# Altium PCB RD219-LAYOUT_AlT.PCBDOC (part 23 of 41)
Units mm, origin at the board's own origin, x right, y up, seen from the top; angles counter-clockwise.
Board outline 209.75 x 159.97 mm, 2 copper layers (TOP, BOTTOM), stack 0 mm thick; 398 components, 199 nets, 1469 pads, 0 vias.
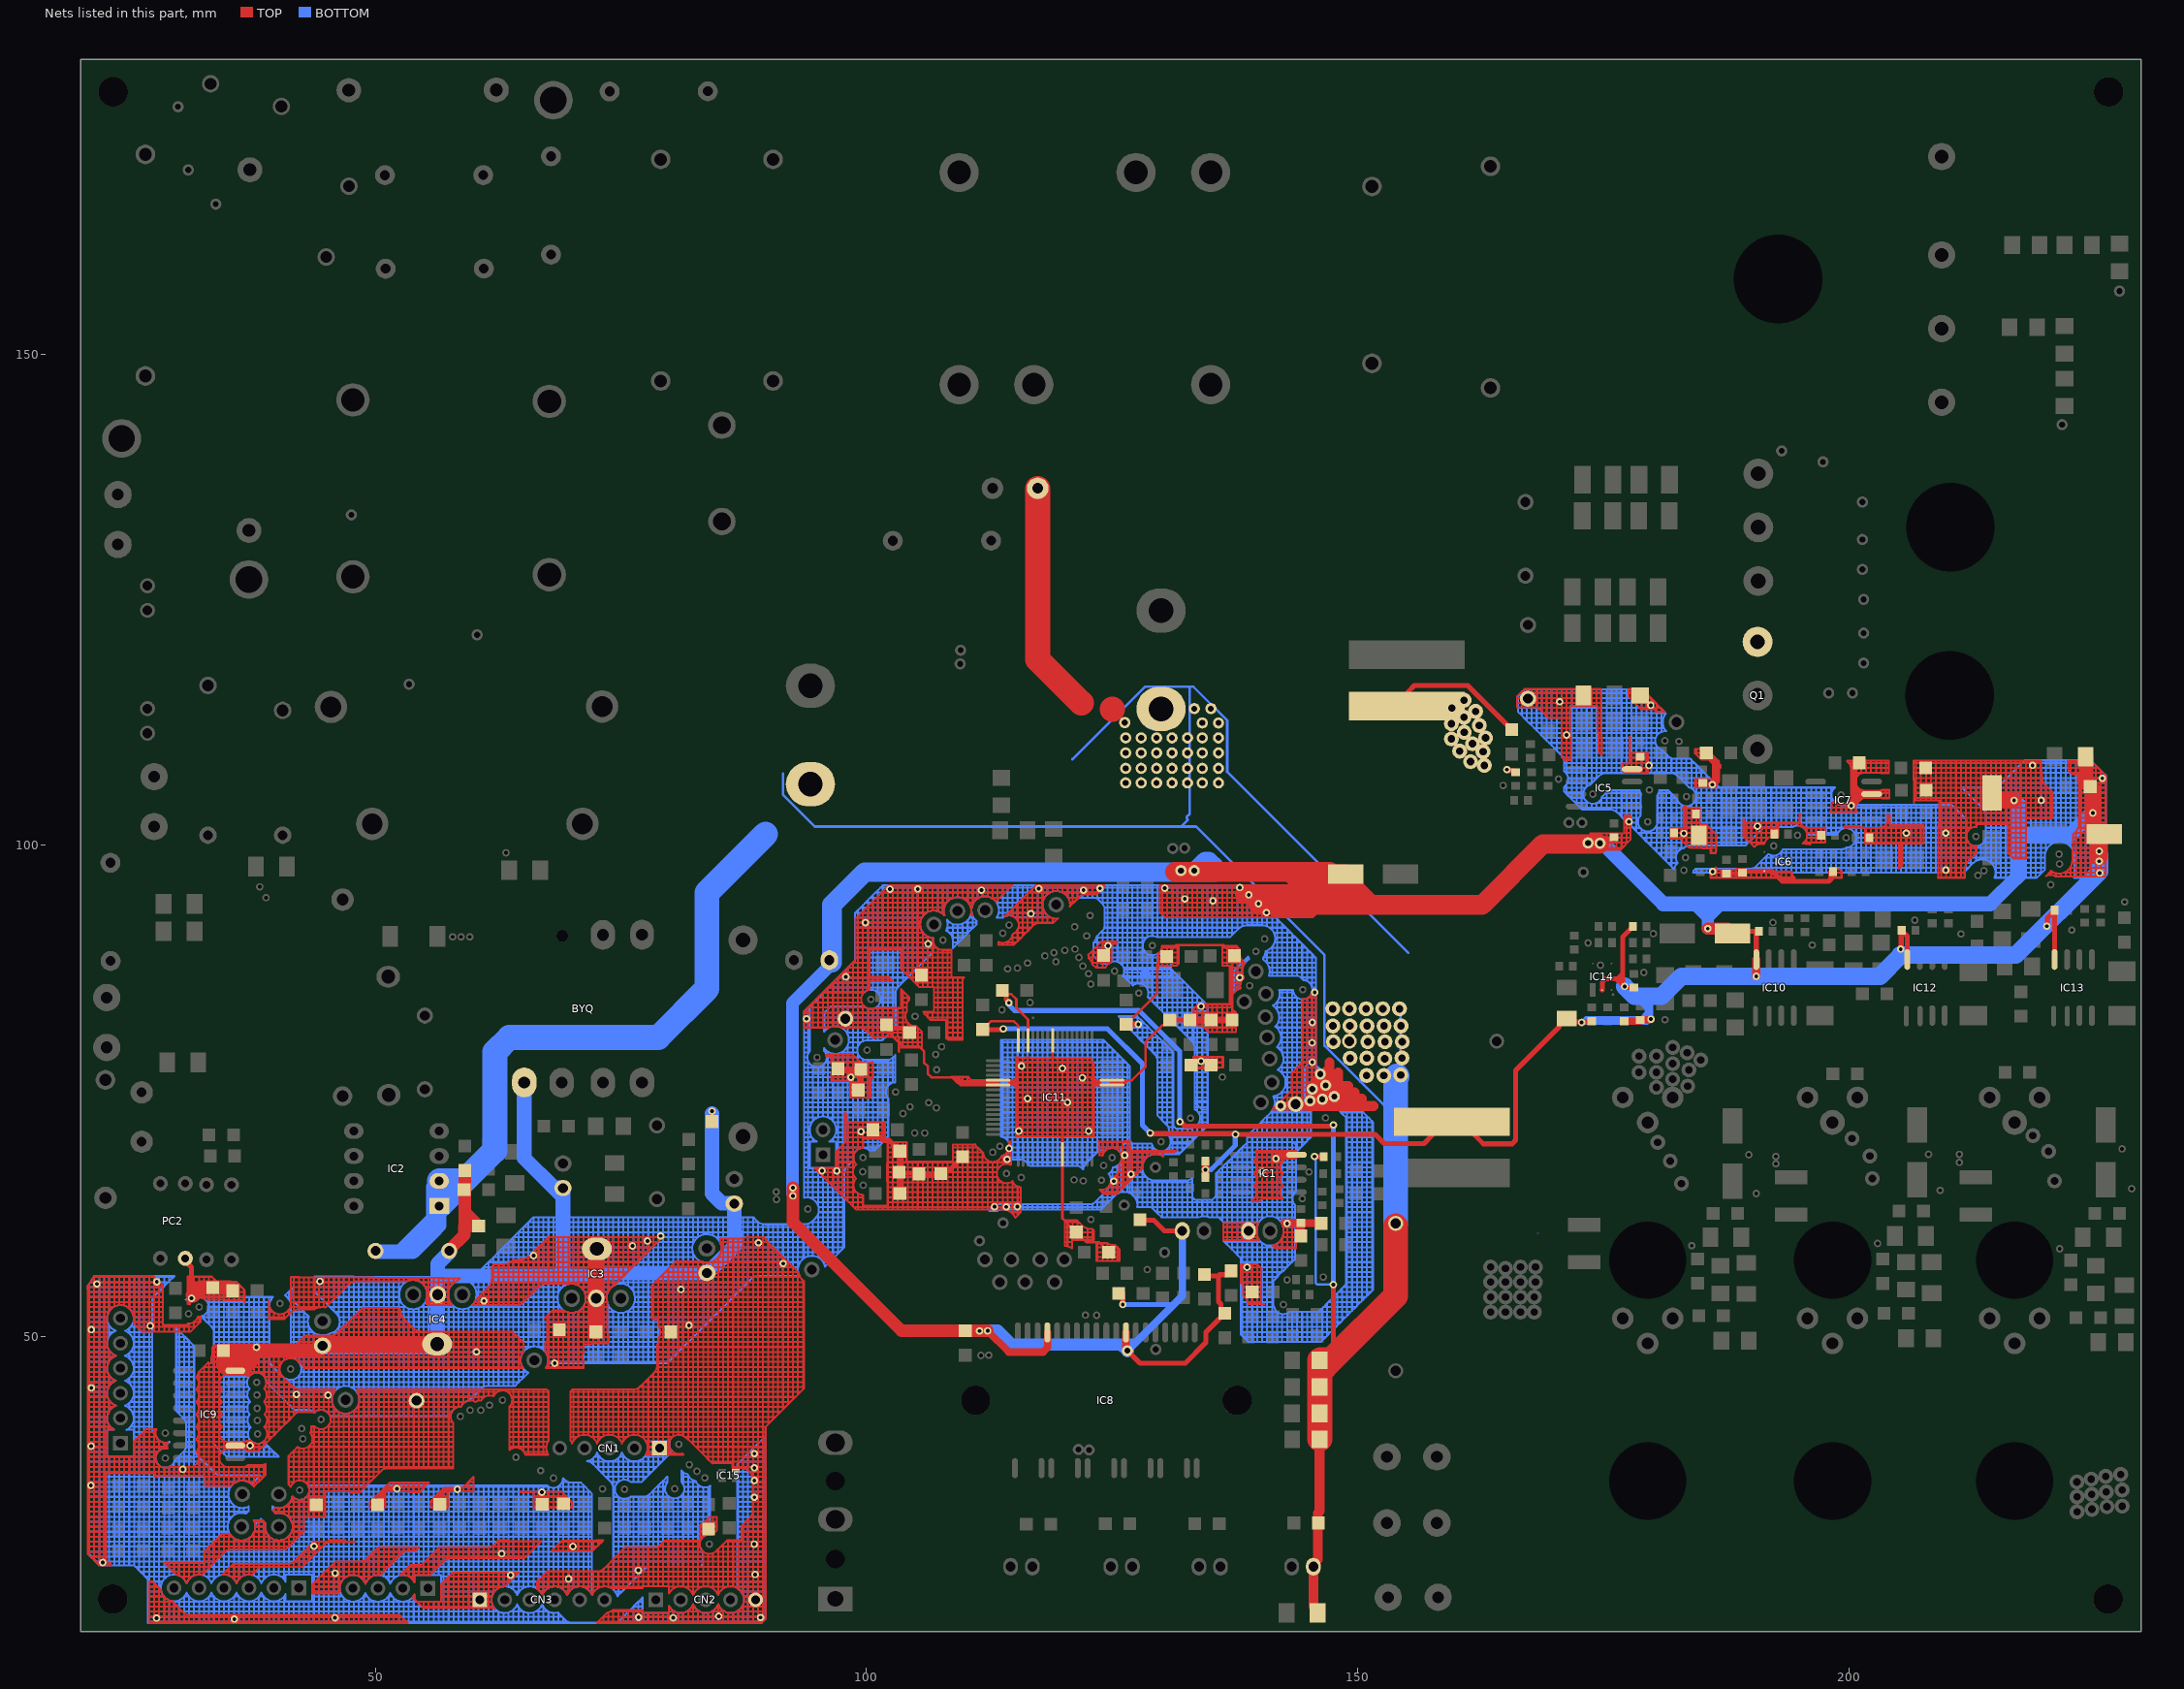
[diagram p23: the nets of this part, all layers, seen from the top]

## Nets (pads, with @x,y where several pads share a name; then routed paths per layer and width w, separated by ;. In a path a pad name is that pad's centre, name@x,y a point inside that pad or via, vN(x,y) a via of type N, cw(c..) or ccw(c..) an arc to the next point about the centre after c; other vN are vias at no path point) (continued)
GND: (continued)
  BOTTOM w0.203: 44.765,23.556 44.765,24.064 ; 44.765,23.556 45.273,23.556 ; 44.765,24.064 44.765,24.572 ; 44.765,24.064 45.273,24.064 ; 44.765,24.572 44.765,25.08 ; 44.765,24.572 45.273,24.572 ; 44.765,25.08 44.765,25.588 ; 44.765,25.08 45.273,25.08 ; 44.765,25.588 44.765,26.096 ; 44.765,25.588 45.273,25.588 ; 44.765,26.096 44.765,26.604 ; 44.765,26.096 45.273,26.096 ; 44.765,26.604 44.765,27.112 ; 44.765,26.604 45.273,26.604 ; 44.765,27.112 44.765,27.62 ; 44.765,27.112 45.273,27.112 ; 44.765,27.62 44.765,28.128 ; 44.765,27.62 45.273,27.62 ; 44.765,28.128 44.765,28.636 ; 44.765,28.128 45.273,28.128 ; 44.765,28.636 44.765,29.144 ; 44.765,28.636 45.273,28.636 ; 44.765,29.144 44.765,29.652 ; 44.765,29.144 45.273,29.144 ; 44.765,29.652 44.765,30.16 ; 44.765,29.652 45.273,29.652 ; 44.765,30.16 44.765,30.668 ; 44.765,30.16 45.273,30.16 ; 44.765,30.668 44.765,31.176 ; 44.765,30.668 45.273,30.668 ; 44.765,31.176 44.765,31.684 ; 44.765,31.176 45.273,31.176 ; 44.765,31.684 44.765,32.192 ; 44.765,31.684 45.273,31.684 ; 44.765,32.192 44.765,32.7 ; 44.765,32.192 45.273,32.192 ; 44.765,32.7 44.765,33.208 ; 44.765,32.7 45.273,32.7 ; 44.765,33.208 44.765,33.716 ; 44.765,33.208 45.273,33.208 ; 44.765,33.716 44.765,34.224 ; 44.765,33.716 45.273,33.716 ; 44.765,34.224 44.765,34.732 ; 44.765,34.224 45.273,34.224 ; 44.765,34.732 44.765,34.866 ; 44.765,34.732 45.273,34.732 ; 44.765,34.866 45.273,34.866 ; 44.765,42.531 cw(c44.482,41.59) 45.101,42.354 cw(c44.482,41.59) 45.103,42.352 ; 44.765,42.531 44.765,42.86 ; 44.765,42.86 44.765,43.368 ; 44.765,42.86 45.273,42.86 ; 44.765,43.368 44.765,43.876 ; 44.765,43.368 45.273,43.368 ; 44.765,43.876 pad.@45.273,43.876 ; 44.765,43.876 44.765,44.384 ; 44.765,44.384 44.765,44.892 ; 44.765,44.384 pad.@45.273,44.384 ; 44.765,44.892 44.765,45.4 ; 44.765,44.892 45.273,44.892 ; 44.765,45.4 45.273,45.4 ; 44.765,45.4 44.765,45.908 ; 44.765,45.908 44.765,46.416 ; 44.765,45.908 45.273,45.908 ; 44.765,46.416 44.765,46.924 ; 44.765,46.416 45.273,46.416 ; 44.765,46.924 44.765,47.432 ; 44.765,46.924 45.273,46.924 ; 44.765,47.432 44.765,47.94 ; 44.765,47.432 45.273,47.432 ; 44.765,47.94 EC6.2@44.765,48.448 ; 44.765,47.94 45.273,47.94 ; EC6.2@44.765,48.448 EC6.2@44.765,48.956 ; EC6.2@44.765,48.448 45.273,48.448 ; EC6.2@44.765,48.956 44.765,49.06 EC6.2@44.765,49.464 ; EC6.2@44.765,48.956 44.869,48.956 EC6.2@45.273,48.956 ; EC6.2@44.765,49.464 44.765,49.972 ; EC6.2@44.765,49.464 EC6.2@45.273,49.464 ; 44.765,49.972 45.273,49.972 ; 44.765,49.972 44.765,50.157 ; 44.765,50.157 ccw(c44.702,51.583) 45.273,50.275 ; 44.765,54.036 44.765,54.544 ; 44.765,54.036 45.273,54.036 ; 44.765,54.544 44.765,55.052 ; 44.765,54.544 45.273,54.544 ; 44.765,55.052 44.765,55.56 ; 44.765,55.052 45.273,55.052 ; 44.765,55.56 45.273,55.56 ; 44.765,55.56 44.765,56.068 ; 44.765,56.068 44.765,56.118 ; 44.765,56.068 45.273,56.068 ; 44.765,56.118 45.273,56.116 ; 44.872,53.528 45.273,53.127 ; 44.872,53.528 45.273,53.528 ; 45.103,42.352 cw(c44.482,41.59) 45.273,42.173 ; 45.103,42.352 45.273,42.352 ; 45.273,20.889 45.273,21.016 ; 45.273,20.889 45.781,20.889 ; 45.273,21.016 45.273,21.524 ; 45.273,21.016 45.781,21.016 ; 45.273,21.524 45.273,22.032 ; 45.273,21.524 pad.@45.781,21.524 ; 45.273,22.032 45.273,22.54 ; 45.273,22.032 45.781,22.032 ; 45.273,22.54 45.273,23.048 ; 45.273,22.54 45.781,22.54 ; 45.273,23.048 45.273,23.556 ; 45.273,23.048 45.781,23.048 ; 45.273,23.556 45.273,24.064 ; 45.273,23.556 45.781,23.556 ; 45.273,24.064 45.273,24.572 ; 45.273,24.064 45.781,24.064 ; 45.273,24.572 45.273,25.08 ; 45.273,24.572 45.781,24.572 ; 45.273,25.08 45.273,25.588 ; 45.273,25.08 45.781,25.08 ; 45.273,25.588 45.273,26.096 ; 45.273,25.588 pad.@45.781,25.588 ; 45.273,26.096 45.273,26.604 ; 45.273,26.096 pad.@45.781,26.096 ; 45.273,26.604 45.273,27.112 ; 45.273,26.604 45.781,26.604 ; 45.273,27.112 45.273,27.62 ; 45.273,27.112 45.781,27.112 ; 45.273,27.62 45.273,28.128 ; 45.273,27.62 45.781,27.62 ; 45.273,28.128 45.273,28.636 ; 45.273,28.128 45.781,28.128 ; 45.273,28.636 45.273,29.144 ; 45.273,28.636 45.781,28.636 ; 45.273,29.144 45.273,29.652 ; 45.273,29.144 45.781,29.144 ; 45.273,29.652 45.273,30.16 ; 45.273,29.652 45.781,29.652 ; 45.273,30.16 45.273,30.668 ; 45.273,30.16 45.781,30.16 ; 45.273,30.668 45.273,31.176 ; 45.273,30.668 45.781,30.668 ; 45.273,31.176 45.273,31.684 ; 45.273,31.176 45.781,31.176 ; 45.273,31.684 45.273,32.192 ; 45.273,31.684 45.781,31.684 ; 45.273,32.192 45.273,32.7 ; 45.273,32.192 45.781,32.192 ; 45.273,32.7 45.273,33.208 ; 45.273,32.7 45.781,32.7 ; 45.273,33.208 45.273,33.716 ; 45.273,33.208 45.781,33.208 ; 45.273,33.716 45.273,34.224 ; 45.273,33.716 45.781,33.716 ; 45.273,34.224 45.273,34.732 ; 45.273,34.224 45.781,34.224 ; 45.273,34.732 45.273,34.866 ; 45.273,34.732 45.781,34.732 ; 45.273,34.866 45.781,34.866 ; 45.273,42.173 45.273,42.352 ; 45.273,42.352 45.273,42.86 ; 45.273,42.352 45.781,42.352 ; 45.273,42.86 45.273,43.368 ; 45.273,42.86 45.774,42.86 ; 45.273,43.368 pad.@45.273,43.876 ; 45.273,43.368 45.593,43.368 ; pad.@45.273,43.876 pad.@45.273,44.384 ; pad.@45.273,43.876 45.61,43.876 ; pad.@45.273,44.384 45.781,44.384 ; pad.@45.273,44.384 45.273,44.892 ; 45.273,44.892 45.273,45.4 ; 45.273,44.892 45.781,44.892 ; 45.273,45.4 45.781,45.4 ; 45.273,45.4 45.273,45.908 ; 45.273,45.908 45.273,46.416 ; 45.273,45.908 45.781,45.908 ; 45.273,46.416 45.273,46.924 ; 45.273,46.416 45.781,46.416 ; 45.273,46.924 45.273,47.432 ; 45.273,46.924 45.781,46.924 ; 45.273,47.432 45.273,47.94 ; 45.273,47.432 45.781,47.432 ; 45.273,47.94 45.273,48.448 ; 45.273,47.94 45.781,47.94 ; 45.273,48.448 EC6.2@45.273,48.956 ; 45.273,48.448 45.781,48.448 ; EC6.2@45.273,48.956 45.781,48.956 ; EC6.2@45.273,48.956 EC6.2@45.273,49.464 ; EC6.2@45.273,49.464 45.273,49.972 ; EC6.2@45.273,49.464 45.781,49.464 ; 45.273,49.972 45.781,49.972 ; 45.273,49.972 45.273,50.275 ; 45.273,50.275 ccw(c44.702,51.583) 45.452,50.369 ; 45.273,53.127 45.273,53.528 ; 45.273,53.127 45.38,53.02 ; 45.273,53.528 45.273,54.036 ; 45.273,53.528 45.781,53.528 ; 45.273,54.036 45.273,54.544 ; 45.273,54.036 45.781,54.036 ; 45.273,54.544 45.273,55.052 ; 45.273,54.544 45.781,54.544 ; 45.273,55.052 45.273,55.56 ; 45.273,55.052 45.781,55.052 ; 45.273,55.56 45.273,56.068 ; 45.273,55.56 45.781,55.56 ; 45.273,56.068 45.273,56.116 ; 45.273,56.068 45.781,56.068 ; 45.273,56.116 45.781,56.115 ; 45.38,53.02 45.781,53.02 ; 45.38,53.02 45.781,52.619 ; 45.593,43.368 cw(c46.979,43.576) 45.608,43.868 cw(c46.979,43.576) 45.61,43.876 ; 45.593,43.368 ccw(c46.979,43.576) 45.595,43.357 ccw(c46.979,43.576) 45.774,42.86 ; 45.774,42.86 ccw(c46.979,43.576) 45.781,42.849 ; 45.781,20.889 45.781,21.016 ; 45.781,20.889 46.289,20.889 ; 45.781,21.016 46.289,21.016 ; 45.781,21.016 pad.@45.781,21.524 ; pad.@45.781,21.524 45.781,22.032 ; pad.@45.781,21.524 46.289,21.524 ; 45.781,22.032 45.781,22.54 ; 45.781,22.032 46.289,22.032 ; 45.781,22.54 45.781,23.048 ; 45.781,22.54 46.289,22.54 ; 45.781,23.048 45.781,23.556 ; 45.781,23.048 46.289,23.048 ; 45.781,23.556 45.781,24.064 ; 45.781,23.556 46.289,23.556 ; 45.781,24.064 45.781,24.572 ; 45.781,24.064 46.289,24.064 ; 45.781,24.572 45.781,25.08 ; 45.781,24.572 46.289,24.572 ; 45.781,25.08 pad.@45.781,25.588 ; 45.781,25.08 46.289,25.08 ; pad.@45.781,25.588 46.289,25.588 ; pad.@45.781,25.588 pad.@45.781,26.096 ; pad.@45.781,26.096 45.781,26.604 ; pad.@45.781,26.096 46.289,26.096 ; 45.781,26.604 45.781,27.112 ; 45.781,26.604 46.289,26.604 ; 45.781,27.112 45.781,27.62 ; 45.781,27.112 46.289,27.112 ; 45.781,27.62 45.781,28.128 ; 45.781,27.62 46.289,27.62 ; 45.781,28.128 45.781,28.636 ; 45.781,28.128 46.289,28.128 ; 45.781,28.636 45.781,29.144 ; 45.781,28.636 46.289,28.636 ; 45.781,29.144 45.781,29.652 ; 45.781,29.144 46.289,29.144 ; 45.781,29.652 45.781,30.16 ; 45.781,29.652 46.289,29.652 ; 45.781,30.16 45.781,30.668 ; 45.781,30.16 46.289,30.16 ; 45.781,30.668 45.781,31.176 ; 45.781,30.668 46.289,30.668 ; 45.781,31.176 45.781,31.684 ; 45.781,31.176 46.289,31.176 ; 45.781,31.684 45.781,32.192 ; 45.781,31.684 46.289,31.684 ; 45.781,32.192 45.781,32.7 ; 45.781,32.192 46.289,32.192 ; 45.781,32.7 45.781,33.208 ; 45.781,32.7 46.289,32.7 ; 45.781,33.208 45.781,33.716 ; 45.781,33.208 46.289,33.208 ; 45.781,33.716 45.781,34.224 ; 45.781,33.716 46.289,33.716 ; 45.781,34.224 45.781,34.732 ; 45.781,34.224 46.289,34.224 ; 45.781,34.732 45.781,34.866 ; 45.781,34.732 46.289,34.732 ; 45.781,34.866 46.289,34.866 ; 45.781,41.938 45.781,42.352 ; 45.781,41.938 46.289,41.938 ; 45.781,42.352 46.289,42.352 ; 45.781,42.352 45.781,42.849 ; 45.781,44.384 45.781,44.892 ; 45.781,44.384 45.833,44.384 ; 45.781,44.892 45.781,45.4 ; 45.781,44.892 46.289,44.892 ; 45.781,45.4 46.289,45.4 ; 45.781,45.4 45.781,45.908 ; 45.781,45.908 45.781,46.416 ; 45.781,45.908 46.289,45.908 ; 45.781,46.416 46.289,46.416 ; 45.781,46.416 45.781,46.924 ; 45.781,46.924 45.781,47.432 ; 45.781,46.924 46.289,46.924 ; 45.781,47.432 46.289,47.432 ; 45.781,47.432 45.781,47.94 ; 45.781,47.94 45.781,48.448 ; 45.781,47.94 46.289,47.94 ; 45.781,48.448 45.781,48.956 ; 45.781,48.448 46.289,48.448 ; 45.781,48.956 45.781,49.464 ; 45.781,48.956 46.289,48.956 ; 45.781,49.464 45.781,49.972 ; 45.781,49.464 46.289,49.464 ; 45.781,49.972 46.289,49.972 ; 45.781,52.619 45.888,52.512 ; 45.781,52.619 45.781,53.02 ; 45.781,53.02 45.781,53.528 ; 45.781,53.02 46.289,53.02 ; 45.781,53.528 45.781,54.036 ; 45.781,53.528 46.289,53.528 ; 45.781,54.036 45.781,54.544 ; 45.781,54.036 46.289,54.036 ; 45.781,54.544 45.781,55.052 ; 45.781,54.544 46.289,54.544 ; 45.781,55.052 45.781,55.56 ; 45.781,55.052 46.289,55.052 ; 45.781,55.56 45.781,56.068 ; 45.781,55.56 46.289,55.56 ; 45.781,56.068 45.781,56.115 ; 45.781,56.068 46.289,56.068 ; 45.781,56.115 46.289,56.113 ; 45.833,44.384 cw(c46.979,43.576) 46.289,44.796 ; 45.888,52.512 46.051,52.349 ; 45.888,52.512 46.289,52.512 ; 46.052,52.348 cw(c45.273,51.569) 46.285,52.004 ; 46.052,52.348 cw(c45.273,51.569) 46.285,52.004 ; 46.27,50.988 ccw(c45.273,51.456) 46.289,51.03 ; 46.27,50.988 46.289,50.988 ; 46.285,52.004 cw(c45.273,51.569) 46.287,51.999 ; 46.285,52.004 cw(c45.273,51.569) 46.287,51.999 ; 46.285,52.004 46.289,52.004 ; 46.287,51.999 cw(c45.273,51.569) 46.289,51.994 ; 46.287,51.999 cw(c45.273,51.569) 46.289,51.994 ; 46.289,20.889 46.289,21.016 ; 46.289,20.889 46.797,20.889 ; 46.289,21.016 46.797,21.016 ; 46.289,21.016 46.289,21.524 ; 46.289,21.524 46.289,22.032 ; 46.289,21.524 46.797,21.524 ; 46.289,22.032 46.289,22.54 ; 46.289,22.032 46.797,22.032 ; 46.289,22.54 46.289,23.048 ; 46.289,22.54 46.797,22.54 ; 46.289,23.048 46.289,23.556 ; 46.289,23.048 46.797,23.048 ; 46.289,23.556 46.289,24.064 ; 46.289,23.556 46.671,23.556 ; 46.289,24.064 46.289,24.572 ; 46.289,24.064 46.419,24.064 ; 46.289,24.572 46.289,25.08 ; 46.289,25.08 46.289,25.588 ; 46.289,25.08 46.562,25.08 ; 46.289,25.588 46.797,25.588 ; 46.289,25.588 46.289,26.096 ; 46.289,26.096 46.289,26.604 ; 46.289,26.096 46.797,26.096 ; 46.289,26.604 46.289,27.112 ; 46.289,26.604 46.797,26.604 ; 46.289,27.112 46.289,27.62 ; 46.289,27.112 46.797,27.112 ; 46.289,27.62 46.289,28.128 ; 46.289,27.62 46.797,27.62 ; 46.289,28.128 46.289,28.636 ; 46.289,28.128 46.797,28.128 ; 46.289,28.636 46.289,29.144 ; 46.289,28.636 46.797,28.636 ; 46.289,29.144 46.289,29.652 ; 46.289,29.144 46.797,29.144 ; 46.289,29.652 46.289,30.16 ; 46.289,29.652 46.797,29.652 ; 46.289,30.16 46.289,30.668 ; 46.289,30.16 46.797,30.16 ; 46.289,30.668 46.289,31.176 ; 46.289,30.668 46.797,30.668 ; 46.289,31.176 46.289,31.684 ; 46.289,31.176 46.797,31.176 ; 46.289,31.684 46.289,32.192 ; 46.289,31.684 46.797,31.684 ; 46.289,32.192 46.289,32.7 ; 46.289,32.192 46.797,32.192 ; 46.289,32.7 46.289,33.208 ; 46.289,32.7 46.797,32.7 ; 46.289,33.208 46.289,33.716 ; 46.289,33.208 46.797,33.208 ; 46.289,33.716 46.289,34.224 ; 46.289,33.716 46.797,33.716 ; 46.289,34.224 46.289,34.732 ; 46.289,34.224 46.797,34.224 ; 46.289,34.732 46.289,34.866 ; 46.289,34.732 46.797,34.732 ; 46.289,34.866 46.797,34.866 ; 46.289,41.938 46.289,42.352 ; 46.289,41.938 46.797,41.938 ; 46.289,44.796 cw(c46.979,43.576) 46.3,44.802 cw(c46.979,43.576) 46.495,44.892 ; 46.289,44.796 46.289,44.892 ; 46.289,44.892 46.289,45.4 ; 46.289,44.892 46.495,44.892 ; 46.289,45.4 46.797,45.4 ; 46.289,45.4 46.289,45.908 ; 46.289,45.908 46.289,46.416 ; 46.289,45.908 46.797,45.908 ; 46.289,46.416 46.289,46.924 ; 46.289,46.416 46.797,46.416 ; 46.289,46.924 46.289,47.432 ; 46.289,46.924 46.797,46.924 ; 46.289,47.432 46.797,47.432 ; 46.289,47.432 46.289,47.94 ; 46.289,47.94 46.289,48.448 ; 46.289,47.94 46.797,47.94 ; 46.289,48.448 46.289,48.956 ; 46.289,48.448 46.797,48.448 ; 46.289,48.956 46.289,49.464 ; 46.289,48.956 46.797,48.956 ; 46.289,49.464 46.289,49.972 ; 46.289,49.464 46.797,49.464 ; 46.289,49.972 46.289,50.48 ; 46.289,49.972 46.797,49.972 ; 46.289,50.48 46.289,50.988 ; 46.289,50.48 46.797,50.48 ; 46.289,50.988 46.797,50.988 ; 46.289,50.988 46.289,51.03 ; 46.289,51.03 ccw(c45.273,51.456) 46.375,51.456 46.375,51.496 ; 46.289,51.994 cw(c45.273,51.569) 46.375,51.569 ; 46.289,51.994 cw(c45.273,51.569) 46.375,51.569 ; 46.289,51.994 46.289,52.004 ; 46.289,52.004 46.797,52.004 ; 46.289,52.004 46.289,52.512 ; 46.289,52.512 46.289,53.02 ; 46.289,52.512 46.797,52.512 ; 46.289,53.02 46.289,53.528 ; 46.289,53.02 46.797,53.02 ; 46.289,53.528 46.289,54.036 ; 46.289,53.528 46.797,53.528 ; 46.289,54.036 46.289,54.544 ; 46.289,54.036 46.797,54.036 ; 46.289,54.544 46.289,55.052 ; 46.289,54.544 46.797,54.544 ; 46.289,55.052 46.289,55.56 ; 46.289,55.052 46.797,55.052 ; 46.289,55.56 46.289,56.068 ; 46.289,55.56 46.797,55.56 ; 46.289,56.068 46.289,56.113 ; 46.289,56.068 46.797,56.068 ; 46.289,56.113 46.797,56.111 ; 46.375,51.496 46.375,51.569 ; 46.375,51.496 46.797,51.496 ; 46.419,24.064 ccw(c47.729,24.397) 46.671,23.556 ; 46.495,44.892 cw(c46.979,43.576) 46.5,44.894 cw(c46.979,43.576) 46.797,44.966 ; 46.671,23.556 ccw(c47.729,24.397) 46.79,23.425 ccw(c47.729,24.397) 46.797,23.418 ; 46.797,20.889 46.797,21.016 ; 46.797,20.889 47.305,20.889 ; 46.797,21.016 46.797,21.524 ; 46.797,21.016 47.305,21.016 ; 46.797,21.524 46.797,22.032 ; 46.797,21.524 47.305,21.524 ; 46.797,22.032 46.797,22.54 ; 46.797,22.032 47.305,22.032 ; 46.797,22.54 46.797,23.048 ; 46.797,22.54 47.305,22.54 ; 46.797,23.048 47.305,23.048 ; 46.797,23.048 46.797,23.418 ; 46.797,25.588 46.797,26.096 ; 46.797,25.588 47.09,25.588 ; 46.797,26.096 46.797,26.604 ; 46.797,26.096 47.305,26.096 ; 46.797,26.604 46.797,27.112 ; 46.797,26.604 47.305,26.604 ; 46.797,27.112 46.797,27.62 ; 46.797,27.112 47.305,27.112 ; 46.797,27.62 46.797,28.128 ; 46.797,27.62 47.305,27.62 ; 46.797,28.128 46.797,28.636 ; 46.797,28.128 47.305,28.128 ; 46.797,28.636 46.797,29.144 ; 46.797,28.636 47.305,28.636 ; 46.797,29.144 46.797,29.652 ; 46.797,29.144 47.305,29.144 ; 46.797,29.652 46.797,30.16 ; 46.797,29.652 47.305,29.652 ; 46.797,30.16 46.797,30.668 ; 46.797,30.16 47.305,30.16 ; 46.797,30.668 46.797,31.176 ; 46.797,30.668 47.305,30.668 ; 46.797,31.176 46.797,31.684 ; 46.797,31.176 47.305,31.176 ; 46.797,31.684 46.797,32.192 ; 46.797,31.684 47.305,31.684 ; 46.797,32.192 46.797,32.7 ; 46.797,32.192 47.305,32.192 ; 46.797,32.7 46.797,33.208 ; 46.797,32.7 47.305,32.7 ; 46.797,33.208 46.797,33.716 ; 46.797,33.208 47.305,33.208 ; 46.797,33.716 46.797,34.224 ; 46.797,33.716 47.305,33.716 ; 46.797,34.224 46.797,34.732 ; 46.797,34.224 47.305,34.224 ; 46.797,34.732 46.797,34.866 ; 46.797,34.732 47.305,34.732 ; 46.797,34.866 47.305,34.866 ; 46.797,41.938 47.305,41.938 ; 46.797,41.938 46.797,42.187 ; 46.797,42.187 ccw(c46.979,43.576) 46.808,42.185 ccw(c46.979,43.576) 47.305,42.213 ; 46.797,44.966 cw(c46.979,43.576) 47.305,44.94 ; 46.797,44.966 46.797,45.4 ; 46.797,45.4 47.305,45.4 ; 46.797,45.4 46.797,45.908 ; 46.797,45.908 46.797,46.416 ; 46.797,45.908 47.305,45.908 ; 46.797,46.416 47.305,46.416 ; 46.797,46.416 46.797,46.924 ; 46.797,46.924 46.797,47.432 ; 46.797,46.924 47.305,46.924 ; 46.797,47.432 47.305,47.432 ; 46.797,47.432 46.797,47.94 ; 46.797,47.94 46.797,48.448 ; 46.797,47.94 47.305,47.94 ; 46.797,48.448 46.797,48.956 ; 46.797,48.448 47.305,48.448 ; 46.797,48.956 46.797,49.464 ; 46.797,48.956 47.305,48.956 ; 46.797,49.464 46.797,49.972 ; 46.797,49.464 47.305,49.464 ; 46.797,49.972 46.797,50.48 ; 46.797,49.972 47.305,49.972 ; 46.797,50.48 46.797,50.988 ; 46.797,50.48 47.305,50.48 ; 46.797,50.988 47.305,50.988 ; 46.797,50.988 46.797,51.496 ; 46.797,51.496 47.305,51.496 ; 46.797,51.496 46.797,52.004 ; 46.797,52.004 46.797,52.512 ; 46.797,52.004 47.305,52.004 ; 46.797,52.512 46.797,53.02 ; 46.797,52.512 47.305,52.512 ; 46.797,53.02 46.797,53.528 ; 46.797,53.02 47.305,53.02 ; 46.797,53.528 46.797,54.036 ; 46.797,53.528 47.305,53.528 ; 46.797,54.036 47.305,54.036 ; 46.797,54.036 46.797,54.544 ; 46.797,54.544 47.305,54.544 ; 46.797,54.544 46.797,55.052 ; 46.797,55.052 46.797,55.56 ; 46.797,55.052 47.305,55.052 ; 46.797,55.56 46.797,56.068 ; 46.797,55.56 47.305,55.56 ; 46.797,56.068 47.305,56.068 ; 46.797,56.068 46.797,56.111 ; 46.797,56.111 47.305,56.11 ; 47.09,25.588 cw(c47.729,24.397) 47.094,25.59 cw(c47.729,24.397) 47.305,25.68 ; 47.305,20.889 47.305,21.016 ; 47.305,20.889 47.813,20.889 ; 47.305,21.016 47.305,21.524 ; 47.305,21.016 47.813,21.016 ; 47.305,21.524 47.305,22.032 ; 47.305,21.524 47.813,21.524 ; 47.305,22.032 47.305,22.54 ; 47.305,22.032 47.813,22.032 ; 47.305,22.54 47.305,23.048 ; 47.305,22.54 47.813,22.54 ; 47.305,23.048 47.645,23.048 ; 47.305,25.68 cw(c47.729,24.397) 47.311,25.682 cw(c47.729,24.397) 47.813,25.746 ; 47.305,25.68 47.305,26.096 ; 47.305,26.096 47.305,26.604 ; 47.305,26.096 47.813,26.096 ; 47.305,26.604 47.305,27.112 ; 47.305,26.604 47.813,26.604 ; 47.305,27.112 47.305,27.62 ; 47.305,27.112 47.813,27.112 ; 47.305,27.62 47.305,28.128 ; 47.305,27.62 47.813,27.62 ; 47.305,28.128 47.305,28.636 ; 47.305,28.128 47.813,28.128 ; 47.305,28.636 47.305,29.144 ; 47.305,28.636 47.813,28.636 ; 47.305,29.144 47.305,29.652 ; 47.305,29.144 47.813,29.144 ; 47.305,29.652 47.305,30.16 ; 47.305,29.652 47.813,29.652 ; 47.305,30.16 47.305,30.668 ; 47.305,30.16 47.813,30.16 ; 47.305,30.668 47.305,31.176 ; 47.305,30.668 47.813,30.668 ; 47.305,31.176 47.305,31.684 ; 47.305,31.176 47.813,31.176 ; 47.305,31.684 47.305,32.192 ; 47.305,31.684 47.813,31.684 ; 47.305,32.192 47.305,32.7 ; 47.305,32.192 47.813,32.192 ; 47.305,32.7 47.305,33.208 ; 47.305,32.7 47.813,32.7 ; 47.305,33.208 47.305,33.716 ; 47.305,33.208 47.813,33.208 ; 47.305,33.716 47.305,34.224 ; 47.305,33.716 47.813,33.716 ; 47.305,34.224 47.305,34.732 ; 47.305,34.224 47.813,34.224 ; 47.305,34.732 47.305,34.866 ; 47.305,34.732 47.813,34.732 ; 47.305,34.866 47.813,34.866 ; 47.305,41.938 47.813,41.938 ; 47.305,41.938 47.305,42.213 ; 47.305,42.213 ccw(c46.979,43.576) 47.661,42.352 ; 47.305,44.94 47.305,45.4 ; 47.305,45.4 47.305,45.908 ; 47.305,45.4 47.813,45.4 ; 47.305,45.908 47.305,46.416 ; 47.305,45.908 47.813,45.908 ; 47.305,46.416 47.305,46.924 ; 47.305,46.416 47.813,46.416 ; 47.305,46.924 47.305,47.432 ; 47.305,46.924 47.813,46.924 ; 47.305,47.432 47.305,47.94 ; 47.305,47.432 47.813,47.432 ; 47.305,47.94 47.305,48.448 ; 47.305,47.94 47.813,47.94 ; 47.305,48.448 47.305,48.956 ; 47.305,48.448 47.813,48.448 ; 47.305,48.956 47.305,49.464 ; 47.305,48.956 47.813,48.956 ; 47.305,49.464 47.305,49.972 ; 47.305,49.464 47.813,49.464 ; 47.305,49.972 47.305,50.48 ; 47.305,49.972 47.813,49.972 ; 47.305,50.48 47.305,50.988 ; 47.305,50.48 47.813,50.48 ; 47.305,50.988 47.305,51.496 ; 47.305,50.988 47.813,50.988 ; 47.305,51.496 47.305,52.004 ; 47.305,51.496 47.813,51.496 ; 47.305,52.004 47.305,52.512 ; 47.305,52.004 47.813,52.004 ; 47.305,52.512 47.305,53.02 ; 47.305,52.512 47.813,52.512 ; 47.305,53.02 47.305,53.528 ; 47.305,53.02 47.813,53.02 ; 47.305,53.528 47.305,54.036 ; 47.305,53.528 47.813,53.528 ; 47.305,54.036 47.305,54.544 ; 47.305,54.036 47.813,54.036 ; 47.305,54.544 47.305,55.052 ; 47.305,54.544 47.813,54.544 ; 47.305,55.052 47.305,55.56 ; 47.305,55.052 47.813,55.052 ; 47.305,55.56 47.305,56.068 ; 47.305,55.56 47.813,55.56 ; 47.305,56.068 47.305,56.11 ; 47.305,56.068 47.813,56.068 ; 47.305,56.11 47.813,56.108 ; 47.661,42.352 47.813,42.352 ; 47.813,20.889 47.813,21.016 ; 47.813,20.889 48.321,20.889 ; 47.813,21.016 47.813,21.524 ; 47.813,21.016 48.321,21.016 ; 47.813,21.524 47.813,22.032 ; 47.813,21.524 48.321,21.524 ; 47.813,22.032 47.813,22.54 ; 47.813,22.032 48.321,22.032 ; 47.813,22.54 48.321,22.54 ; 47.813,22.54 47.813,23.048 ; 47.813,23.048 ccw(c47.729,24.397) 48.321,23.182 ; 47.813,23.048 48.321,23.048 ; 47.813,25.746 cw(c47.729,24.397) 48.321,25.612 ; 47.813,25.746 47.813,26.096 ; 47.813,26.096 47.813,26.604 ; 47.813,26.096 48.321,26.096 ; 47.813,26.604 47.813,27.112 ; 47.813,26.604 48.321,26.604 ; 47.813,27.112 47.813,27.62 ; 47.813,27.112 48.321,27.112 ; 47.813,27.62 47.813,28.128 ; 47.813,27.62 48.321,27.62 ; 47.813,28.128 47.813,28.636 ; 47.813,28.128 48.321,28.128 ; 47.813,28.636 47.813,29.144 ; 47.813,28.636 48.321,28.636 ; 47.813,29.144 47.813,29.652 ; 47.813,29.144 48.321,29.144 ; 47.813,29.652 47.813,30.16 ; 47.813,29.652 48.321,29.652 ; 47.813,30.16 47.813,30.668 ; 47.813,30.16 48.321,30.16 ; 47.813,30.668 47.813,31.176 ; 47.813,30.668 48.321,30.668 ; 47.813,31.176 47.813,31.684 ; 47.813,31.176 48.321,31.176 ; 47.813,31.684 47.813,32.192 ; 47.813,31.684 48.321,31.684 ; 47.813,32.192 47.813,32.7 ; 47.813,32.192 48.321,32.192 ; 47.813,32.7 47.813,33.208 ; 47.813,32.7 48.321,32.7 ; 47.813,33.208 47.813,33.716 ; 47.813,33.208 48.321,33.208 ; 47.813,33.716 47.813,34.224 ; 47.813,33.716 48.321,33.716 ; 47.813,34.224 47.813,34.732 ; 47.813,34.224 48.321,34.224 ; 47.813,34.732 47.813,34.866 ; 47.813,34.732 48.321,34.732 ; 47.813,34.866 48.321,34.866 ; 47.813,41.938 47.813,42.352 ; 47.813,41.938 48.321,41.938 ; 47.813,42.352 48.321,42.352 ; 47.813,44.703 cw(c46.979,43.576) 47.823,44.696 cw(c46.979,43.576) 48.125,44.384 ; 47.813,44.703 47.813,44.892 ; 47.813,44.892 47.813,45.4 ; 47.813,44.892 48.321,44.892 ; 47.813,45.4 47.813,45.908 ; 47.813,45.4 48.321,45.4 ; 47.813,45.908 47.813,46.416 ; 47.813,45.908 48.321,45.908 ; 47.813,46.416 47.813,46.924 ; 47.813,46.416 48.321,46.416 ; 47.813,46.924 47.813,47.432 ; 47.813,46.924 48.321,46.924 ; 47.813,47.432 47.813,47.94 ; 47.813,47.432 48.321,47.432 ; 47.813,47.94 47.813,48.448 ; 47.813,47.94 48.321,47.94 ; 47.813,48.448 47.813,48.956 ; 47.813,48.448 48.321,48.448 ; 47.813,48.956 47.813,49.464 ; 47.813,48.956 48.321,48.956 ; 47.813,49.464 47.813,49.972 ; 47.813,49.464 48.321,49.464 ; 47.813,49.972 47.813,50.48 ; 47.813,49.972 48.321,49.972 ; 47.813,50.48 47.813,50.988 ; 47.813,50.48 48.321,50.48 ; 47.813,50.988 47.813,51.496 ; 47.813,50.988 48.321,50.988 ; 47.813,51.496 47.813,52.004 ; 47.813,51.496 48.321,51.496 ; 47.813,52.004 47.813,52.512 ; 47.813,52.004 48.321,52.004 ; 47.813,52.512 47.813,53.02 ; 47.813,52.512 48.321,52.512 ; 47.813,53.02 47.813,53.528 ; 47.813,53.02 48.321,53.02 ; 47.813,53.528 47.813,54.036 ; 47.813,53.528 48.321,53.528 ; 47.813,54.036 47.813,54.544 ; 47.813,54.036 48.321,54.036 ; 47.813,54.544 47.813,55.052 ; 47.813,54.544 48.321,54.544 ; 47.813,55.052 47.813,55.56 ; 47.813,55.052 48.321,55.052 ; 47.813,55.56 47.813,56.068 ; 47.813,55.56 48.321,55.56 ; 47.813,56.068 47.813,56.108 ; 47.813,56.068 48.321,56.068 ; 47.813,56.108 48.321,56.106 ; 48.125,44.384 cw(c46.979,43.576) 48.127,44.38 cw(c46.979,43.576) 48.321,43.981 ; 48.125,44.384 48.321,44.384 ; 48.184,42.86 ccw(c46.979,43.576) 48.319,43.167 ccw(c46.979,43.576) 48.321,43.172 ; 48.184,42.86 48.321,42.86 ; 48.321,20.889 48.321,21.016 ; 48.321,20.889 48.829,20.889 ; 48.321,21.016 48.321,21.524 ; 48.321,21.016 48.829,21.016 ; 48.321,21.524 48.321,22.032 ; 48.321,21.524 48.829,21.524 ; 48.321,22.032 48.321,22.54 ; 48.321,22.032 48.829,22.032 ; 48.321,22.54 48.321,23.048 ; 48.321,22.54 48.829,22.54 ; 48.321,23.048 48.829,23.048 ; 48.321,23.048 48.321,23.182 ; 48.321,23.182 ccw(c47.729,24.397) 48.787,23.556 ; 48.321,25.612 48.321,26.096 ; 48.321,26.096 48.321,26.604 ; 48.321,26.096 48.829,26.096 ; 48.321,26.604 48.321,27.112 ; 48.321,26.604 48.829,26.604 ; 48.321,27.112 48.321,27.62 ; 48.321,27.112 48.829,27.112 ; 48.321,27.62 48.321,28.128 ; 48.321,27.62 48.829,27.62 ; 48.321,28.128 48.321,28.636 ; 48.321,28.128 48.829,28.128 ; 48.321,28.636 48.321,29.144 ; 48.321,28.636 48.829,28.636 ; 48.321,29.144 48.321,29.652 ; 48.321,29.144 48.829,29.144 ; 48.321,29.652 48.321,30.16 ; 48.321,29.652 48.829,29.652 ; 48.321,30.16 48.321,30.668 ; 48.321,30.16 48.829,30.16 ; 48.321,30.668 48.321,31.176 ; 48.321,30.668 48.829,30.668 ; 48.321,31.176 48.321,31.684 ; 48.321,31.176 48.829,31.176 ; 48.321,31.684 48.321,32.192 ; 48.321,31.684 48.829,31.684 ; 48.321,32.192 48.321,32.7 ; 48.321,32.192 48.829,32.192 ; 48.321,32.7 48.321,33.208 ; 48.321,32.7 48.829,32.7 ; 48.321,33.208 48.321,33.716 ; 48.321,33.208 48.829,33.208 ; 48.321,33.716 48.321,34.224 ; 48.321,33.716 48.829,33.716 ; 48.321,34.224 48.321,34.732 ; 48.321,34.224 48.829,34.224 ; 48.321,34.732 48.321,34.866 ; 48.321,34.732 48.829,34.732 ; 48.321,34.866 48.829,34.866 ; 48.321,41.938 48.321,42.352 ; 48.321,41.938 48.829,41.938 ; 48.321,42.352 48.321,42.86 ; 48.321,42.352 48.829,42.352 ; 48.321,42.86 48.829,42.86 ; 48.321,42.86 48.321,43.172 ; 48.321,43.172 ccw(c46.979,43.576) 48.365,43.368 ; 48.321,43.981 cw(c46.979,43.576) 48.348,43.876 ; 48.321,43.981 48.321,44.384 ; 48.321,44.384 48.321,44.892 ; 48.321,44.384 48.829,44.384 ; 48.321,44.892 48.321,45.4 ; 48.321,44.892 48.829,44.892 ; 48.321,45.4 48.321,45.908 ; 48.321,45.4 48.829,45.4 ; 48.321,45.908 48.321,46.416 ; 48.321,45.908 48.829,45.908 ; 48.321,46.416 48.321,46.924 ; 48.321,46.416 48.829,46.416 ; 48.321,46.924 48.321,47.432 ; 48.321,46.924 48.829,46.924 ; 48.321,47.432 48.321,47.94 ; 48.321,47.432 48.829,47.432 ; 48.321,47.94 48.321,48.448 ; 48.321,47.94 48.829,47.94 ; 48.321,48.448 48.321,48.956 ; 48.321,48.448 48.829,48.448 ; 48.321,48.956 48.321,49.464 ; 48.321,48.956 48.829,48.956 ; 48.321,49.464 48.321,49.972 ; 48.321,49.464 48.829,49.464 ; 48.321,49.972 48.321,50.48 ; 48.321,49.972 48.829,49.972 ; 48.321,50.48 48.321,50.988 ; 48.321,50.48 48.829,50.48 ; 48.321,50.988 48.321,51.496 ; 48.321,50.988 48.829,50.988 ; 48.321,51.496 48.321,52.004 ; 48.321,51.496 48.829,51.496 ; 48.321,52.004 48.321,52.512 ; 48.321,52.004 48.829,52.004 ; 48.321,52.512 48.321,53.02 ; 48.321,52.512 48.829,52.512 ; 48.321,53.02 48.321,53.528 ; 48.321,53.02 48.829,53.02 ; 48.321,53.528 48.321,54.036 ; 48.321,53.528 48.829,53.528 ; 48.321,54.036 48.321,54.544 ; 48.321,54.036 48.829,54.036 ; 48.321,54.544 48.321,55.052 ; 48.321,54.544 48.829,54.544 ; 48.321,55.052 48.321,55.56 ; 48.321,55.052 48.829,55.052 ; 48.321,55.56 48.321,56.068 ; 48.321,55.56 48.829,55.56 ; 48.321,56.068 48.321,56.106 ; 48.321,56.068 48.829,56.068 ; 48.321,56.106 48.829,56.105 ; 48.348,43.876 cw(c46.979,43.576) 48.35,43.868 cw(c46.979,43.576) 48.381,43.576 cw(c46.979,43.576) 48.365,43.368 ; 48.348,43.876 48.829,43.876 ; 48.365,43.368 48.829,43.368 ; 48.787,23.556 ccw(c47.729,24.397) 48.829,23.612 ; 48.787,23.556 48.829,23.556 ; 48.829,20.889 48.829,21.016 ; 48.829,20.889 49.337,20.889 ; 48.829,21.016 48.829,21.524 ; 48.829,21.016 49.337,21.016 ; 48.829,21.524 48.829,22.032 ; 48.829,21.524 49.337,21.524 ; 48.829,22.032 48.829,22.54 ; 48.829,22.032 49.337,22.032 ; 48.829,22.54 48.829,23.048 ; 48.829,22.54 49.337,22.54 ; 48.829,23.048 48.829,23.556 ; 48.829,23.048 49.337,23.048 ; 48.829,23.556 48.829,23.612 ; 48.829,23.556 49.211,23.556 ; 48.829,25.182 cw(c47.729,24.397) 48.895,25.08 ; 48.829,25.182 48.829,25.588 ; 48.829,25.588 48.829,26.096 ; 48.829,25.588 49.337,25.588 ; 48.829,26.096 48.829,26.604 ; 48.829,26.096 49.337,26.096 ; 48.829,26.604 48.829,27.112 ; 48.829,26.604 49.337,26.604 ; 48.829,27.112 48.829,27.62 ; 48.829,27.112 49.337,27.112 ; 48.829,27.62 48.829,28.128 ; 48.829,27.62 49.337,27.62 ; 48.829,28.128 48.829,28.636 ; 48.829,28.128 49.337,28.128 ; 48.829,28.636 48.829,29.144 ; 48.829,28.636 49.337,28.636 ; 48.829,29.144 48.829,29.652 ; 48.829,29.144 49.337,29.144 ; 48.829,29.652 48.829,30.16 ; 48.829,29.652 49.337,29.652 ; 48.829,30.16 48.829,30.668 ; 48.829,30.16 49.337,30.16 ; 48.829,30.668 48.829,31.176 ; 48.829,30.668 49.337,30.668 ; 48.829,31.176 48.829,31.684 ; 48.829,31.176 49.337,31.176 ; 48.829,31.684 48.829,32.192 ; 48.829,31.684 49.337,31.684 ; 48.829,32.192 48.829,32.7 ; 48.829,32.192 49.337,32.192 ; 48.829,32.7 48.829,33.208 ; 48.829,32.7 49.337,32.7 ; 48.829,33.208 48.829,33.716 ; 48.829,33.208 49.337,33.208 ; 48.829,33.716 48.829,34.224 ; 48.829,33.716 49.337,33.716 ; 48.829,34.224 48.829,34.732 ; 48.829,34.224 49.337,34.224 ; 48.829,34.732 48.829,34.866 ; 48.829,34.732 49.337,34.732 ; 48.829,34.866 49.337,34.866 ; 48.829,41.938 48.829,42.352 ; 48.829,41.938 49.337,41.938 ; 48.829,42.352 48.829,42.86 ; 48.829,42.352 49.337,42.352 ; 48.829,42.86 48.829,43.368 ; 48.829,42.86 49.337,42.86 ; 48.829,43.368 48.829,43.876 ; 48.829,43.368 49.337,43.368 ; 48.829,43.876 48.829,44.384 ; 48.829,43.876 49.337,43.876 ; 48.829,44.384 48.829,44.892 ; 48.829,44.384 49.337,44.384 ; 48.829,44.892 48.829,45.4 ; 48.829,44.892 49.337,44.892 ; 48.829,45.4 48.829,45.908 ; 48.829,45.4 49.337,45.4 ; 48.829,45.908 48.829,46.416 ; 48.829,45.908 49.337,45.908 ; 48.829,46.416 48.829,46.924 ; 48.829,46.416 49.337,46.416 ; 48.829,46.924 48.829,47.432 ; 48.829,46.924 49.337,46.924 ; 48.829,47.432 48.829,47.94 ; 48.829,47.432 49.337,47.432 ; 48.829,47.94 48.829,48.448 ; 48.829,47.94 49.337,47.94 ; 48.829,48.448 48.829,48.956 ; 48.829,48.448 49.337,48.448 ; 48.829,48.956 48.829,49.464 ; 48.829,48.956 49.337,48.956 ; 48.829,49.464 48.829,49.972 ; 48.829,49.464 49.337,49.464 ; 48.829,49.972 48.829,50.48 ; 48.829,49.972 49.337,49.972 ; 48.829,50.48 48.829,50.988 ; 48.829,50.48 49.337,50.48 ; 48.829,50.988 48.829,51.496 ; 48.829,50.988 49.337,50.988 ; 48.829,51.496 48.829,52.004 ; 48.829,51.496 49.337,51.496 ; 48.829,52.004 48.829,52.512 ; 48.829,52.004 49.337,52.004 ; 48.829,52.512 48.829,53.02 ; 48.829,52.512 49.337,52.512 ; 48.829,53.02 48.829,53.528 ; 48.829,53.02 49.337,53.02 ; 48.829,53.528 48.829,54.036 ; 48.829,53.528 49.337,53.528 ; 48.829,54.036 48.829,54.544 ; 48.829,54.036 49.337,54.036 ; 48.829,54.544 48.829,55.052 ; 48.829,54.544 49.337,54.544 ; 48.829,55.052 48.829,55.56 ; 48.829,55.052 49.337,55.052 ; 48.829,55.56 48.829,56.068 ; 48.829,55.56 49.337,55.56 ; 48.829,56.068 48.829,56.105 ; 48.829,56.068 49.337,56.068 ; 48.829,56.105 49.337,56.103 ; 48.895,25.08 cw(c47.729,24.397) 48.899,25.073 cw(c47.729,24.397) 48.999,24.86 cw(c50.269,24.397) 49.098,25.073 cw(c50.269,24.397) 49.102,25.08 ; 48.895,25.08 49.102,25.08 ; 49.211,23.556 ccw(c50.269,24.397) 49.33,23.425 ccw(c50.269,24.397) 49.337,23.418 ; 49.337,20.889 49.337,21.016 ; 49.337,20.889 49.845,20.889 ; 49.337,21.016 49.337,21.524 ; 49.337,21.016 49.845,21.016 ; 49.337,21.524 49.337,22.032 ; 49.337,21.524 49.845,21.524 ; 49.337,22.032 49.337,22.54 ; 49.337,22.032 49.845,22.032 ; 49.337,22.54 49.337,23.048 ; 49.337,22.54 49.845,22.54 ; 49.337,23.048 49.845,23.048 ; 49.337,23.048 49.337,23.418 ; 49.337,25.588 49.337,26.096 ; 49.337,25.588 49.63,25.588 ; 49.337,26.096 49.337,26.604 ; 49.337,26.096 49.845,26.096 ; 49.337,26.604 49.337,27.112 ; 49.337,26.604 49.845,26.604 ; 49.337,27.112 49.337,27.62 ; 49.337,27.112 49.845,27.112 ; 49.337,27.62 49.337,28.128 ; 49.337,27.62 49.845,27.62 ; 49.337,28.128 49.337,28.636 ; 49.337,28.128 49.845,28.128 ; 49.337,28.636 49.337,29.144 ; 49.337,28.636 49.845,28.636 ; 49.337,29.144 49.337,29.652 ; 49.337,29.144 49.845,29.144 ; 49.337,29.652 49.337,30.16 ; 49.337,29.652 49.845,29.652 ; 49.337,30.16 49.337,30.668 ; 49.337,30.16 49.845,30.16 ; 49.337,30.668 49.337,31.176 ; 49.337,30.668 49.845,30.668 ; 49.337,31.176 49.337,31.684 ; 49.337,31.176 49.845,31.176 ; 49.337,31.684 49.337,32.192 ; 49.337,31.684 49.845,31.684 ; 49.337,32.192 49.337,32.7 ; 49.337,32.192 49.845,32.192 ; 49.337,32.7 49.337,33.208 ; 49.337,32.7 49.845,32.7 ; 49.337,33.208 49.337,33.716 ; 49.337,33.208 49.845,33.208 ; 49.337,33.716 49.337,34.224 ; 49.337,33.716 49.845,33.716 ; 49.337,34.224 49.337,34.732 ; 49.337,34.224 49.845,34.224 ; 49.337,34.732 49.337,34.866 ; 49.337,34.732 49.845,34.732 ; 49.337,34.866 49.845,34.866 ; 49.337,41.938 49.337,42.352 ; 49.337,41.938 49.845,41.938 ; 49.337,42.352 49.337,42.86 ; 49.337,42.352 49.845,42.352 ; 49.337,42.86 49.337,43.368 ; 49.337,42.86 49.845,42.86 ; 49.337,43.368 49.337,43.876 ; 49.337,43.368 49.845,43.368 ; 49.337,43.876 49.337,44.384 ; 49.337,43.876 49.845,43.876 ; 49.337,44.384 49.337,44.892 ; 49.337,44.384 49.845,44.384 ; 49.337,44.892 49.337,45.4 ; 49.337,44.892 49.845,44.892 ; 49.337,45.4 49.337,45.908 ; 49.337,45.4 49.845,45.4 ; 49.337,45.908 49.337,46.416 ; 49.337,45.908 49.845,45.908 ; 49.337,46.416 49.337,46.924 ; 49.337,46.416 49.845,46.416 ; 49.337,46.924 49.337,47.432 ; 49.337,46.924 49.845,46.924 ; 49.337,47.432 49.337,47.94 ; 49.337,47.432 49.845,47.432 ; 49.337,47.94 49.337,48.448 ; 49.337,47.94 49.845,47.94 ; 49.337,48.448 49.337,48.956 ; 49.337,48.448 49.845,48.448 ; 49.337,48.956 49.337,49.464 ; 49.337,48.956 49.845,48.956 ; 49.337,49.464 49.337,49.972 ; 49.337,49.464 49.845,49.464 ; 49.337,49.972 49.337,50.48 ; 49.337,49.972 49.845,49.972 ; 49.337,50.48 49.337,50.988 ; 49.337,50.48 49.845,50.48 ; 49.337,50.988 49.337,51.496 ; 49.337,50.988 49.845,50.988 ; 49.337,51.496 49.337,52.004 ; 49.337,51.496 49.845,51.496 ; 49.337,52.004 49.337,52.512 ; 49.337,52.004 49.845,52.004 ; 49.337,52.512 49.337,53.02 ; 49.337,52.512 49.845,52.512 ; 49.337,53.02 49.337,53.528 ; 49.337,53.02 49.845,53.02 ; 49.337,53.528 49.337,54.036 ; 49.337,53.528 49.845,53.528 ; 49.337,54.036 49.337,54.544 ; 49.337,54.036 49.845,54.036 ; 49.337,54.544 49.337,55.052 ; 49.337,54.544 49.845,54.544 ; 49.337,55.052 49.337,55.56 ; 49.337,55.052 49.845,55.052 ; 49.337,55.56 49.337,56.068 ; 49.337,55.56 49.845,55.56 ; 49.337,56.068 49.337,56.103 ; 49.337,56.068 49.845,56.068 ; 49.337,56.103 49.845,56.101 ; 49.63,25.588 cw(c50.269,24.397) 49.634,25.59 cw(c50.269,24.397) 49.845,25.68 ; 49.845,20.889 49.845,21.016 ; 49.845,20.889 50.353,20.889 ; 49.845,21.016 49.845,21.524 ; 49.845,21.016 50.353,21.016 ; 49.845,21.524 49.845,22.032 ; 49.845,21.524 50.353,21.524 ; 49.845,22.032 49.845,22.54 ; 49.845,22.032 50.353,22.032 ; 49.845,22.54 49.845,23.048 ; 49.845,22.54 50.353,22.54 ; 49.845,23.048 50.185,23.048 ; 49.845,25.68 cw(c50.269,24.397) 49.851,25.682 cw(c50.269,24.397) 50.353,25.746 ; 49.845,25.68 49.845,26.096 ; 49.845,26.096 49.845,26.604 ; 49.845,26.096 50.353,26.096 ; 49.845,26.604 49.845,27.112 ; 49.845,26.604 50.353,26.604 ; 49.845,27.112 49.845,27.62 ; 49.845,27.112 50.353,27.112 ; 49.845,27.62 49.845,28.128 ; 49.845,27.62 50.353,27.62 ; 49.845,28.128 49.845,28.636 ; 49.845,28.128 50.353,28.128 ; 49.845,28.636 49.845,29.144 ; 49.845,28.636 50.353,28.636 ; 49.845,29.144 49.845,29.652 ; 49.845,29.144 50.353,29.144 ; 49.845,29.652 49.845,30.16 ; 49.845,29.652 50.353,29.652 ; 49.845,30.16 49.845,30.668 ; 49.845,30.16 50.353,30.16 ; 49.845,30.668 49.845,31.176 ; 49.845,30.668 50.353,30.668 ; 49.845,31.176 49.845,31.684 ; 49.845,31.176 50.353,31.176 ; 49.845,31.684 49.845,32.192 ; 49.845,31.684 50.353,31.684 ; 49.845,32.192 49.845,32.7 ; 49.845,32.192 50.353,32.192 ; 49.845,32.7 49.845,33.208 ; 49.845,32.7 50.353,32.7 ; 49.845,33.208 49.845,33.716 ; 49.845,33.208 50.353,33.208 ; 49.845,33.716 49.845,34.224 ; 49.845,33.716 50.353,33.716 ; 49.845,34.224 49.845,34.732 ; 49.845,34.224 50.353,34.224 ; 49.845,34.732 49.845,34.866 ; 49.845,34.732 50.353,34.732 ; 49.845,34.866 50.353,34.866 ; 49.845,41.938 49.845,42.352 ; 49.845,41.938 50.353,41.938 ; 49.845,42.352 49.845,42.86 ; 49.845,42.352 50.353,42.352 ; 49.845,42.86 49.845,43.368 ; 49.845,42.86 50.353,42.86 ; 49.845,43.368 49.845,43.876 ; 49.845,43.368 50.353,43.368 ; 49.845,43.876 49.845,44.384 ; 49.845,43.876 50.353,43.876 ; 49.845,44.384 49.845,44.892 ; 49.845,44.384 50.353,44.384 ; 49.845,44.892 49.845,45.4 ; 49.845,44.892 50.353,44.892 ; 49.845,45.4 49.845,45.908 ; 49.845,45.4 50.353,45.4 ; 49.845,45.908 49.845,46.416 ; 49.845,45.908 50.353,45.908 ; 49.845,46.416 49.845,46.924 ; 49.845,46.416 50.353,46.416 ; 49.845,46.924 49.845,47.432 ; 49.845,46.924 50.353,46.924 ; 49.845,47.432 49.845,47.94 ; 49.845,47.432 50.353,47.432 ; 49.845,47.94 49.845,48.448 ; 49.845,47.94 50.353,47.94 ; 49.845,48.448 49.845,48.956 ; 49.845,48.448 50.353,48.448 ; 49.845,48.956 49.845,49.464 ; 49.845,48.956 50.353,48.956 ; 49.845,49.464 49.845,49.972 ; 49.845,49.464 50.353,49.464 ; 49.845,49.972 49.845,50.48 ; 49.845,49.972 50.353,49.972 ; 49.845,50.48 49.845,50.988 ; 49.845,50.48 50.353,50.48 ; 49.845,50.988 49.845,51.496 ; 49.845,50.988 50.353,50.988 ; 49.845,51.496 49.845,52.004 ; 49.845,51.496 50.353,51.496 ; 49.845,52.004 49.845,52.512 ; 49.845,52.004 50.353,52.004 ; 49.845,52.512 49.845,53.02 ; 49.845,52.512 50.353,52.512 ; 49.845,53.02 49.845,53.528 ; 49.845,53.02 50.353,53.02 ; 49.845,53.528 49.845,54.036 ; 49.845,53.528 50.353,53.528 ; 49.845,54.036 49.845,54.544 ; 49.845,54.036 50.353,54.036 ; 49.845,54.544 49.845,55.052 ; 49.845,54.544 50.353,54.544 ; 49.845,55.052 49.845,55.56 ; 49.845,55.052 50.353,55.052 ; 49.845,55.56 49.845,56.068 ; 49.845,55.56 50.353,55.56 ; 49.845,56.068 49.845,56.101 ; 49.845,56.068 50.353,56.068 ; 49.845,56.101 50.353,56.1 ; 50.353,20.889 50.353,21.016 ; 50.353,20.889 50.861,20.889 ; 50.353,21.016 50.353,21.524 ; 50.353,21.016 50.861,21.016 ; 50.353,21.524 50.353,22.032 ; 50.353,21.524 50.861,21.524 ; 50.353,22.032 50.353,22.54 ; 50.353,22.032 50.861,22.032 ; 50.353,22.54 50.861,22.54 ; 50.353,22.54 50.353,23.048 ; 50.353,23.048 ccw(c50.269,24.397) 50.861,23.182 ; 50.353,23.048 50.861,23.048 ; 50.353,25.746 cw(c50.269,24.397) 50.861,25.612 ; 50.353,25.746 50.353,26.096 ; 50.353,26.096 50.353,26.604 ; 50.353,26.096 50.861,26.096 ; 50.353,26.604 50.353,27.112 ; 50.353,26.604 50.861,26.604 ; 50.353,27.112 50.353,27.62 ; 50.353,27.112 50.861,27.112 ; 50.353,27.62 50.353,28.128 ; 50.353,27.62 50.861,27.62 ; 50.353,28.128 50.353,28.636 ; 50.353,28.128 50.861,28.128 ; 50.353,28.636 50.353,29.144 ; 50.353,28.636 50.861,28.636 ; 50.353,29.144 50.353,29.652 ; 50.353,29.144 50.861,29.144 ; 50.353,29.652 50.353,30.16 ; 50.353,29.652 50.861,29.652 ; 50.353,30.16 50.353,30.668 ; 50.353,30.16 50.861,30.16 ; 50.353,30.668 50.353,31.176 ; 50.353,30.668 50.861,30.668 ; 50.353,31.176 50.353,31.684 ; 50.353,31.176 50.861,31.176 ; 50.353,31.684 50.353,32.192 ; 50.353,31.684 50.861,31.684 ; 50.353,32.192 50.353,32.7 ; 50.353,32.192 50.861,32.192 ; 50.353,32.7 50.353,33.208 ; 50.353,32.7 50.861,32.7 ; 50.353,33.208 50.353,33.716 ; 50.353,33.208 50.861,33.208 ; 50.353,33.716 50.353,34.224 ; 50.353,33.716 50.861,33.716 ; 50.353,34.224 50.353,34.732 ; 50.353,34.224 50.861,34.224 ; 50.353,34.732 50.353,34.866 ; 50.353,34.732 50.861,34.732 ; 50.353,34.866 50.861,34.866 ; 50.353,41.938 50.353,42.352 ; 50.353,41.938 50.861,41.938 ; 50.353,42.352 50.353,42.86 ; 50.353,42.352 50.861,42.352 ; 50.353,42.86 50.353,43.368 ; 50.353,42.86 50.861,42.86 ; 50.353,43.368 50.353,43.876 ; 50.353,43.368 50.861,43.368 ; 50.353,43.876 50.353,44.384 ; 50.353,43.876 50.861,43.876 ; 50.353,44.384 50.353,44.892 ; 50.353,44.384 50.861,44.384 ; 50.353,44.892 50.353,45.4 ; 50.353,44.892 50.861,44.892 ; 50.353,45.4 50.353,45.908 ; 50.353,45.4 50.861,45.4 ; 50.353,45.908 50.353,46.416 ; 50.353,45.908 50.861,45.908 ; 50.353,46.416 50.353,46.924 ; 50.353,46.416 50.861,46.416 ; 50.353,46.924 50.353,47.432 ; 50.353,46.924 50.861,46.924 ; 50.353,47.432 50.353,47.94 ; 50.353,47.432 50.861,47.432 ; 50.353,47.94 50.353,48.448 ; 50.353,47.94 50.861,47.94 ; 50.353,48.448 50.353,48.956 ; 50.353,48.448 50.861,48.448 ; 50.353,48.956 50.353,49.464 ; 50.353,48.956 50.861,48.956 ; 50.353,49.464 50.353,49.972 ; 50.353,49.464 50.861,49.464 ; 50.353,49.972 50.353,50.48 ; 50.353,49.972 50.861,49.972 ; 50.353,50.48 50.353,50.988 ; 50.353,50.48 50.861,50.48 ; 50.353,50.988 50.353,51.496 ; 50.353,50.988 50.861,50.988 ; 50.353,51.496 50.353,52.004 ; 50.353,51.496 50.861,51.496 ; 50.353,52.004 50.353,52.512 ; 50.353,52.004 50.861,52.004 ; 50.353,52.512 50.353,53.02 ; 50.353,52.512 50.861,52.512 ; 50.353,53.02 50.353,53.528 ; 50.353,53.02 50.861,53.02 ; 50.353,53.528 50.353,54.036 ; 50.353,53.528 50.861,53.528 ; 50.353,54.036 50.353,54.544 ; 50.353,54.036 50.861,54.036 ; 50.353,54.544 50.353,55.052 ; 50.353,54.544 50.861,54.544 ; 50.353,55.052 50.353,55.56 ; 50.353,55.052 50.861,55.052 ; 50.353,55.56 50.353,56.068 ; 50.353,55.56 50.861,55.56 ; 50.353,56.068 50.353,56.1 ; 50.353,56.068 50.861,56.068 ; 50.353,56.1 50.861,56.098 ; 50.861,20.889 50.861,21.016 ; 50.861,20.889 51.369,20.889 ; 50.861,21.016 50.861,21.524 ; 50.861,21.016 51.369,21.016 ; 50.861,21.524 50.861,22.032 ; 50.861,21.524 51.369,21.524 ; 50.861,22.032 50.861,22.54 ; 50.861,22.032 51.369,22.032 ; 50.861,22.54 50.861,23.048 ; 50.861,22.54 51.369,22.54 ; 50.861,23.048 51.369,23.048 ; 50.861,23.048 50.861,23.182 ; 50.861,23.182 ccw(c50.269,24.397) 51.327,23.556 ; 50.861,25.612 50.861,26.096 ; 50.861,26.096 50.861,26.604 ; 50.861,26.096 51.369,26.096 ; 50.861,26.604 50.861,27.112 ; 50.861,26.604 51.369,26.604 ; 50.861,27.112 50.861,27.62 ; 50.861,27.112 51.369,27.112 ; 50.861,27.62 50.861,28.128 ; 50.861,27.62 51.369,27.62 ; 50.861,28.128 50.861,28.636 ; 50.861,28.128 51.369,28.128 ; 50.861,28.636 50.861,29.144 ; 50.861,28.636 51.369,28.636 ; 50.861,29.144 50.861,29.652 ; 50.861,29.144 51.369,29.144 ; 50.861,29.652 50.861,30.16 ; 50.861,29.652 51.369,29.652 ; 50.861,30.16 50.861,30.668 ; 50.861,30.16 51.369,30.16 ; 50.861,30.668 50.861,31.176 ; 50.861,30.668 51.369,30.668 ; 50.861,31.176 50.861,31.684 ; 50.861,31.176 51.369,31.176 ; 50.861,31.684 50.861,32.192 ; 50.861,31.684 51.369,31.684 ; 50.861,32.192 50.861,32.7 ; 50.861,32.192 51.369,32.192 ; 50.861,32.7 50.861,33.208 ; 50.861,32.7 51.369,32.7 ; 50.861,33.208 50.861,33.716 ; 50.861,33.208 51.369,33.208 ; 50.861,33.716 50.861,34.224 ; 50.861,33.716 51.369,33.716 ; 50.861,34.224 50.861,34.732 ; 50.861,34.224 51.369,34.224 ; 50.861,34.732 50.861,34.866 ; 50.861,34.732 51.369,34.732 ; 50.861,34.866 51.369,34.866 ; 50.861,41.938 50.861,42.352 ; 50.861,41.938 51.369,41.938 ; 50.861,42.352 50.861,42.86 ; 50.861,42.352 51.369,42.352 ; 50.861,42.86 50.861,43.368 ; 50.861,42.86 51.369,42.86 ; 50.861,43.368 50.861,43.876 ; 50.861,43.368 51.369,43.368 ; 50.861,43.876 50.861,44.384 ; 50.861,43.876 51.369,43.876 ; 50.861,44.384 50.861,44.892 ; 50.861,44.384 51.369,44.384 ; 50.861,44.892 50.861,45.4 ; 50.861,44.892 51.369,44.892 ; 50.861,45.4 50.861,45.908 ; 50.861,45.4 51.369,45.4 ; 50.861,45.908 50.861,46.416 ; 50.861,45.908 51.369,45.908 ; 50.861,46.416 50.861,46.924 ; 50.861,46.416 51.369,46.416 ; 50.861,46.924 50.861,47.432 ; 50.861,46.924 51.369,46.924 ; 50.861,47.432 50.861,47.94 ; 50.861,47.432 51.369,47.432 ; 50.861,47.94 50.861,48.448 ; 50.861,47.94 51.369,47.94 ; 50.861,48.448 50.861,48.956 ; 50.861,48.448 51.369,48.448 ; 50.861,48.956 50.861,49.464 ; 50.861,48.956 51.369,48.956 ; 50.861,49.464 50.861,49.972 ; 50.861,49.464 51.369,49.464 ; 50.861,49.972 50.861,50.48 ; 50.861,49.972 51.369,49.972 ; 50.861,50.48 50.861,50.988 ; 50.861,50.48 51.369,50.48 ; 50.861,50.988 50.861,51.496 ; 50.861,50.988 51.369,50.988 ; 50.861,51.496 50.861,52.004 ; 50.861,51.496 51.369,51.496 ; 50.861,52.004 50.861,52.512 ; 50.861,52.004 51.369,52.004 ; 50.861,52.512 50.861,53.02 ; 50.861,52.512 51.369,52.512 ; 50.861,53.02 50.861,53.528 ; 50.861,53.02 51.369,53.02 ; 50.861,53.528 50.861,54.036 ; 50.861,53.528 51.369,53.528 ; 50.861,54.036 50.861,54.544 ; 50.861,54.036 51.369,54.036 ; 50.861,54.544 50.861,55.052 ; 50.861,54.544 51.369,54.544 ; 50.861,55.052 50.861,55.56 ; 50.861,55.052 51.369,55.052 ; 50.861,55.56 50.861,56.068 ; 50.861,55.56 51.369,55.56 ; 50.861,56.068 50.861,56.098 ; 50.861,56.068 51.369,56.068 ; 50.861,56.098 51.369,56.096 ; 51.327,23.556 ccw(c50.269,24.397) 51.369,23.612 ; 51.327,23.556 51.369,23.556 ; 51.369,20.889 51.369,21.016 ; 51.369,20.889 51.877,20.889 ; 51.369,21.016 51.369,21.524 ; 51.369,21.016 51.877,21.016 ; 51.369,21.524 51.369,22.032 ; 51.369,21.524 51.877,21.524 ; 51.369,22.032 51.369,22.54 ; 51.369,22.032 51.877,22.032 ; 51.369,22.54 51.369,23.048 ; 51.369,22.54 51.877,22.54 ; 51.369,23.048 51.369,23.556 ; 51.369,23.048 51.877,23.048 ; 51.369,23.556 51.751,23.556 ; 51.369,23.556 51.369,23.612 ; 51.369,25.182 cw(c50.269,24.397) 51.435,25.08 ; 51.369,25.182 51.369,25.588 ; 51.369,25.588 51.369,26.096 ; 51.369,25.588 51.877,25.588 ; 51.369,26.096 51.369,26.604 ; 51.369,26.096 51.877,26.096 ; 51.369,26.604 51.369,27.112 ; 51.369,26.604 51.877,26.604 ; 51.369,27.112 51.369,27.62 ; 51.369,27.112 51.877,27.112 ; 51.369,27.62 51.369,28.128 ; 51.369,27.62 51.877,27.62 ; 51.369,28.128 51.369,28.636 ; 51.369,28.128 51.877,28.128 ; 51.369,28.636 51.369,29.144 ; 51.369,28.636 51.877,28.636 ; 51.369,29.144 51.369,29.652 ; 51.369,29.144 51.877,29.144 ; 51.369,29.652 51.369,30.16 ; 51.369,29.652 51.877,29.652 ; 51.369,30.16 51.369,30.668 ; 51.369,30.16 51.877,30.16 ; 51.369,30.668 51.369,31.176 ; 51.369,30.668 51.877,30.668 ; 51.369,31.176 51.369,31.684 ; 51.369,31.176 51.877,31.176 ; 51.369,31.684 51.369,32.192 ; 51.369,31.684 51.877,31.684 ; 51.369,32.192 51.369,32.7 ; 51.369,32.192 51.877,32.192 ; 51.369,32.7 51.369,33.208 ; 51.369,32.7 51.877,32.7 ; 51.369,33.208 51.369,33.716 ; 51.369,33.208 51.877,33.208 ; 51.369,33.716 51.369,34.224 ; 51.369,33.716 51.877,33.716 ; 51.369,34.224 51.369,34.732 ; 51.369,34.224 51.877,34.224 ; 51.369,34.732 51.369,34.866 ; 51.369,34.732 51.877,34.732 ; 51.369,34.866 51.877,34.866 ; 51.369,41.938 51.369,42.352 ; 51.369,41.938 51.877,41.938 ; 51.369,42.352 51.369,42.86 ; 51.369,42.352 51.877,42.352 ; 51.369,42.86 51.369,43.368 ; 51.369,42.86 51.877,42.86 ; 51.369,43.368 51.369,43.876 ; 51.369,43.368 51.877,43.368 ; 51.369,43.876 51.369,44.384 ; 51.369,43.876 51.877,43.876 ; 51.369,44.384 51.369,44.892 ; 51.369,44.384 51.877,44.384 ; 51.369,44.892 51.369,45.4 ; 51.369,44.892 51.877,44.892 ; 51.369,45.4 51.369,45.908 ; 51.369,45.4 51.877,45.4 ; 51.369,45.908 51.369,46.416 ; 51.369,45.908 51.877,45.908 ; 51.369,46.416 51.369,46.924 ; 51.369,46.416 51.877,46.416 ; 51.369,46.924 51.369,47.432 ; 51.369,46.924 51.877,46.924 ; 51.369,47.432 51.369,47.94 ; 51.369,47.432 51.877,47.432 ; 51.369,47.94 51.369,48.448 ; 51.369,47.94 51.877,47.94 ; 51.369,48.448 51.369,48.956 ; 51.369,48.448 51.877,48.448 ; 51.369,48.956 51.369,49.464 ; 51.369,48.956 51.877,48.956 ; 51.369,49.464 51.369,49.972 ; 51.369,49.464 51.877,49.464 ; 51.369,49.972 51.369,50.48 ; 51.369,49.972 51.877,49.972 ; 51.369,50.48 51.369,50.988 ; 51.369,50.48 51.877,50.48 ; 51.369,50.988 51.369,51.496 ; 51.369,50.988 51.877,50.988 ; 51.369,51.496 51.369,52.004 ; 51.369,51.496 51.877,51.496 ; 51.369,52.004 51.369,52.512 ; 51.369,52.004 51.877,52.004 ; 51.369,52.512 51.369,53.02 ; 51.369,52.512 51.877,52.512 ; 51.369,53.02 51.369,53.528 ; 51.369,53.02 51.877,53.02 ; 51.369,53.528 51.369,54.036 ; 51.369,53.528 51.877,53.528 ; 51.369,54.036 51.369,54.544 ; 51.369,54.036 51.877,54.036 ; 51.369,54.544 51.369,55.052 ; 51.369,54.544 51.877,54.544 ; 51.369,55.052 51.369,55.56 ; 51.369,55.052 51.877,55.052 ; 51.369,55.56 51.369,56.068 ; 51.369,55.56 51.877,55.56 ; 51.369,56.068 51.369,56.096 ; 51.369,56.068 51.877,56.068 ; 51.369,56.096 51.877,56.095 ; 51.435,25.08 cw(c50.269,24.397) 51.439,25.073 cw(c50.269,24.397) 51.539,24.86 cw(c52.809,24.397) 51.638,25.073 cw(c52.809,24.397) 51.642,25.08 ; 51.435,25.08 51.642,25.08 ; 51.751,23.556 ccw(c52.809,24.397) 51.877,23.418 ; 51.877,20.889 51.877,21.016 ; 51.877,20.889 52.385,20.889 ; 51.877,21.016 51.877,21.524 ; 51.877,21.016 52.385,21.016 ; 51.877,21.524 51.877,22.032 ; 51.877,21.524 52.385,21.524 ; 51.877,22.032 51.877,22.54 ; 51.877,22.032 52.385,22.032 ; 51.877,22.54 51.877,23.048 ; 51.877,22.54 52.385,22.54 ; 51.877,23.048 52.385,23.048 ; 51.877,23.048 51.877,23.418 ; 51.877,25.588 51.877,26.096 ; 51.877,25.588 52.17,25.588 ; 51.877,26.096 51.877,26.604 ; 51.877,26.096 52.385,26.096 ; 51.877,26.604 51.877,27.112 ; 51.877,26.604 52.385,26.604 ; 51.877,27.112 51.877,27.62 ; 51.877,27.112 52.385,27.112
